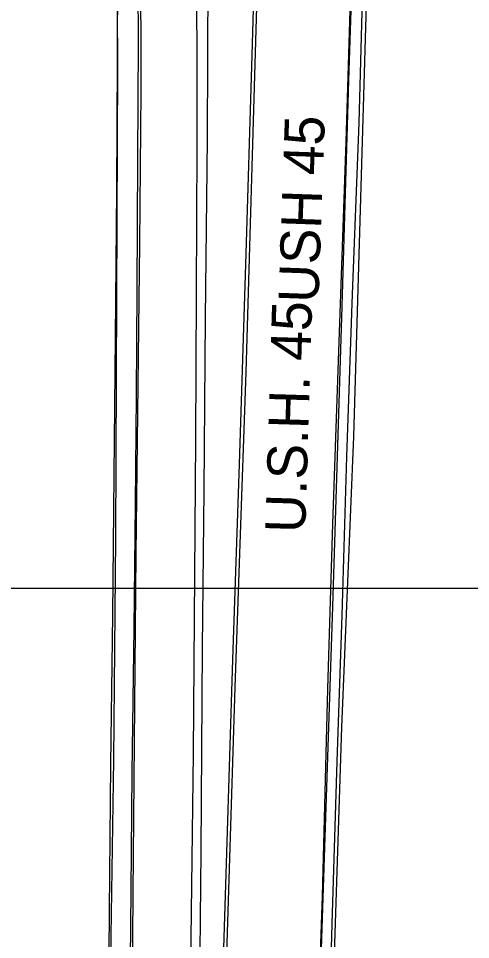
# Model space of a CAD drawing. Extents: x 353423 to 364002, y 127000 to 201942.
# Drawn here: x 361357.4 to 361470.4, y 131912.1 to 132142.6 of the extents above; entities that cross this region are included whole.
import ezdxf

# ---------------------------------------------------------------- set-up
doc = ezdxf.new("R2010")
doc.units = 0
for name, color, linetype in [('E_DTM_SlopeTop', 7, 'Continuous'), ('E_LAND_TreeLine', 7, 'Continuous'), ('E_RW_IP', 7, 'Continuous')]:
    doc.layers.add(name, color=color, linetype=linetype)

msp = doc.modelspace()

# ---------------------------------------------------------------- linework, layer by layer
at = {"layer": 'E_DTM_SlopeTop'}
for points in [[(361464.86, 132976.42), (361463.91, 132906.98), (361461.73, 132832.23), (361459.86, 132768.05), (361457.85, 132696.75), (361455.67, 132625.71), (361453.62, 132560.67), (361451.05, 132485.72), (361448.89, 132404.98), (361446.76, 132344.1), (361444.57, 132270.14), (361442.39, 132202.43), (361439.91, 132127.01), (361438.1, 132067.85), (361435.92, 131995.48), (361433.75, 131930.16), (361431.26, 131854.06), (361428.74, 131770.89), (361425.76, 131686.63)], [(361430.16, 131701.25), (361432.11, 131769.04), (361434.08, 131831.72), (361436.21, 131903.29), (361438.21, 131965.27), (361441.2, 132038.01), (361443.74, 132123.15), (361446.01, 132200.48), (361447.68, 132265.76), (361449.97, 132342.45), (361452.49, 132428.72), (361454.55, 132486.96), (361457.23, 132581.29), (361459.23, 132650.77), (361462.07, 132729.55), (361463.85, 132802.85), (361466.65, 132872.95), (361467.83, 132941.11), (361468.79, 132976.08)], [(361382.82, 131645.67), (361383.66, 131706.48), (361384.51, 131786.08), (361385.45, 131845.88), (361386.02, 131923.66), (361386.78, 132008.6), (361387.69, 132086.22), (361388.02, 132124.3), (361387.98, 132159.95), (361386.49, 132215.67), (361384.63, 132267.99), (361381.61, 132321.39), (361377.11, 132378.72), (361372.64, 132427.53), (361367.15, 132475.91), (361360.11, 132527.54), (361351.65, 132583.36), (361339.44, 132654.21), (361329.03, 132707.61), (361316.5, 132764.48), (361306.42, 132807.97), (361292.18, 132864.05), (361268.84, 132946.34)], [(361306.62, 132783.09), (361317.32, 132735.17), (361326.14, 132692.89), (361333.83, 132653.34), (361341.74, 132609.5), (361348.12, 132572.55), (361353, 132538.45), (361358.49, 132499.45), (361363.08, 132461.46), (361367.66, 132422.52), (361371.26, 132383.27), (361374.72, 132340.17), (361377.77, 132294.56), (361379.9, 132249.28), (361381.43, 132202.89), (361381.91, 132174.81), (361382.14, 132130.34), (361381.89, 132072.84), (361381.6, 132012.57), (361381.1, 131957.1), (361380.16, 131891.06), (361379.21, 131819), (361378.3, 131741.31), (361377.36, 131657.69)], [(361402.47, 131708.5), (361403.61, 131748.04), (361405.15, 131797.25), (361406.55, 131840.33), (361407.95, 131886.05), (361409.49, 131933.8), (361410.97, 131982.15), (361412.67, 132031.07), (361414.24, 132081), (361415.79, 132133.35), (361417.08, 132176.81), (361418.6, 132224.98), (361420.29, 132278), (361421.87, 132332.44), (361423.58, 132383.2), (361425.48, 132438.64), (361427.02, 132487.77), (361428.48, 132532.73), (361429.65, 132577.86), (361430.83, 132613.31), (361431.54, 132638.48)], [(361426.78, 131719.89), (361427.54, 131748.12), (361428.88, 131787.86), (361430.24, 131832.07), (361431.74, 131875.77), (361433.35, 131922.98), (361434.73, 131974.84), (361435.99, 132016.13), (361437.67, 132064.09), (361439.33, 132111.67), (361440.8, 132161.15), (361441.72, 132192.29), (361443.23, 132237.42), (361444.48, 132282.34), (361446.01, 132328.42), (361447.07, 132369.59), (361448.21, 132415.19), (361450.05, 132467.24), (361451.4, 132504.26), (361452.5, 132544.18), (361453.88, 132587.84), (361455.41, 132632.51)], [(361400.59, 131711.35), (361400.59, 131719.25), (361400.95, 131744.48), (361401.46, 131781.52), (361402.02, 131818.7), (361402.31, 131857.26), (361402.6, 131892.16), (361403.02, 131934.2), (361403.36, 131985.09), (361403.82, 132024.52), (361404.13, 132067.64), (361404.64, 132112.45), (361404.84, 132153.23), (361404.47, 132182.91), (361403.8, 132210.96), (361402.99, 132232.93), (361402.89, 132234.99)], [(361401.88, 132168.85), (361401.98, 132110.49), (361401.66, 132037.12), (361401.06, 131958.7), (361400.06, 131879.49), (361399.11, 131788.7), (361398.78, 131707.05), (361398.56, 131558.6), (361405.66, 131787.76), (361409.25, 131900.44), (361411.56, 131975.27), (361414.27, 132054.07), (361417.03, 132148.36)], [(361383.35, 131709.2), (361383.72, 131741.62), (361384.26, 131782.17), (361384.4, 131816.48), (361384.76, 131852.69), (361385.23, 131889.78), (361385.59, 131924.25), (361385.8, 131953.82), (361386.29, 131989.99), (361386.63, 132021.16), (361386.89, 132048.14), (361387.04, 132074.59), (361387.18, 132107.43), (361387.38, 132136.5), (361387.18, 132165.21)], [(361429.61, 131707.52), (361430.27, 131736.76), (361431.43, 131772.95), (361432.46, 131808.98), (361433.61, 131839.32), (361434.81, 131879.73), (361435.84, 131916.1), (361437.09, 131956.64), (361438.34, 131993.24), (361439.48, 132032.99), (361440.89, 132073.56), (361442.54, 132116.47), (361443.61, 132156.59)], [(361377.97, 131708.73), (361378.33, 131732.07), (361378.77, 131762.35), (361378.97, 131793.31), (361379.35, 131828.61), (361379.59, 131860.57), (361379.89, 131887.63), (361380.16, 131919.21), (361380.5, 131955.89), (361380.98, 131993.4), (361381.27, 132028.28), (361381.66, 132062.74), (361382, 132099.59), (361382.1, 132132.35), (361382.25, 132154.32)]]:
    msp.add_lwpolyline(points, dxfattribs=at)
at = {"layer": 'E_LAND_TreeLine'}
msp.add_line((360000, 132000), (364000, 132000), dxfattribs=at)

# ---------------------------------------------------------------- texts
at = {"layer": 'E_RW_IP'}
for s, rotation, p in [('USH 45', 87.9986, (361432.36, 132071.29)), ('U.S.H. 45', 88.2795, (361429.06, 132013.74))]:
    msp.add_text(s, height=10, rotation=rotation, dxfattribs=at).set_placement(p)

doc.saveas('drawing.dxf')
